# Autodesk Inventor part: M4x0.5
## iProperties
IsCustomPart: 1
Company: 한국ATC센터
Created: 2014-10
Part Number: M4x0.5
Material: 강, 연강
Description: 6각머리 태핑 나사
Document SubType Name: Modeling
Standard: KS B 1003
Designer: 한국ATC센터
Standards Organization: KS
Language: ko-KR
Size Designation: M 4 x 16
Categories: <MemberInstance><Categories><Category DisplayName="조임쇠" InternalName="e4da775c-781d-43d5-af7c-5136215cf5a6" Mnemonic="FSTN"><Category DisplayName="볼트" InternalN
Density: 7.86 g/cm^3
Mass: 2.62973 g
Surface Area: 3.81119 cm^2
Volume: 0.334572 cm^3
Author: KYOUNG IL JANG
Revision Number: 1
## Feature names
1. Fillet2
